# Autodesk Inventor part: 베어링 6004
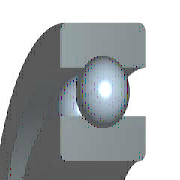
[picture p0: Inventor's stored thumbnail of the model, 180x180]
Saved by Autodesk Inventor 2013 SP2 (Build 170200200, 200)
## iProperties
Created: 2012-02
Part Number: 베어링 6004
Material: 강철, 연강
Description: 깊은 그루브 볼 베어링
Document SubType Name: Modeling
Standard: KS B 2023
Designer: mduedu
Standards Organization: KS
Language: ko-KR
Size Designation: 6004 - 20 x 42 x 12
Categories: <MemberInstance><Categories><Category DisplayName="샤프트 부품" InternalName="7f7aeb1f-a693-4053-b835-cee3144e0d98" Mnemonic="SHFT"><Category DisplayName="베어링" Inter
Density: 1 g/cm^3
IsCustomPart: 1
Author: mduedu
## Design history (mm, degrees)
sketch "스케치" dims "d0" = 5.72 (= -0.26 x WD + 0.26 x BD)
  geometry: L1 (3.14, 15.5)-(8.86, 15.5); L2 (6, 15.5)-(6, 12.64); L3 (6, 15.5)-(6, 18.36); L4 (3.875, 13.586)-(0, 13.586); L5 (0, 10)-(12, 10); L6 (3.875, 17.414)-(0, 17.414); L7 (0, 21)-(12, 21); L8 (12, 10)-(12, 13.586); L9 (8.125, 13.586)-(12, 13.586); L10 (8.125, 17.414)-(12, 17.414); L11 (12, 21)-(12, 17.414); L12 (-1.4, 0)-(8.4, 0) reference; L13 (0, -0.3)-(0, 5.3) reference
  constraints: 22 end point, 4 point on line, 2 collinear, 2 perpendicular, 2 symmetric about line, 1 midpoint, 1 parallel, 14 other
  dimensions: "d9" = 20 diameter of L5 L12 (= WD); "d11" = 42 diameter of L7 L12 (= BD); "d12" = 12 distance between parallel lines of L8 L13 (= KB); "d13" = 27.172 diameter of L9 L12 (= 0.326 x BD + 0.674 x WD)
revolve "본체" stored, may be unused: angle "d6" = 90 deg
revolve "볼" stored, may be unused: angle "d7" = 90 deg
pattern_circular "IDS_ARRAYBALL[SIMPL:T]" dims angle "d3" = 360 deg
body "Solid1"
fillet "모깎기1" dims "d1" = 0.6 (= KRS)
other parameters: "WD" = 20 [user parameter; used in 5 equation terms], "BD" = 42 [user parameter; used in 5 equation terms], "KB" = 12 [user parameter; used in 1 equation term], "KRS" = 0.6 [user parameter; used in 1 equation term], "d4" = 0, "d5" = 0, "d8" = 0, "d14" = 0, "d15" = 0, "BBA" = 0 [user parameter], "BC0" = 5000000 [user parameter], "BC" = 9360000 [user parameter], "BR" = 21 (= 0.5 x BD) [user parameter]
